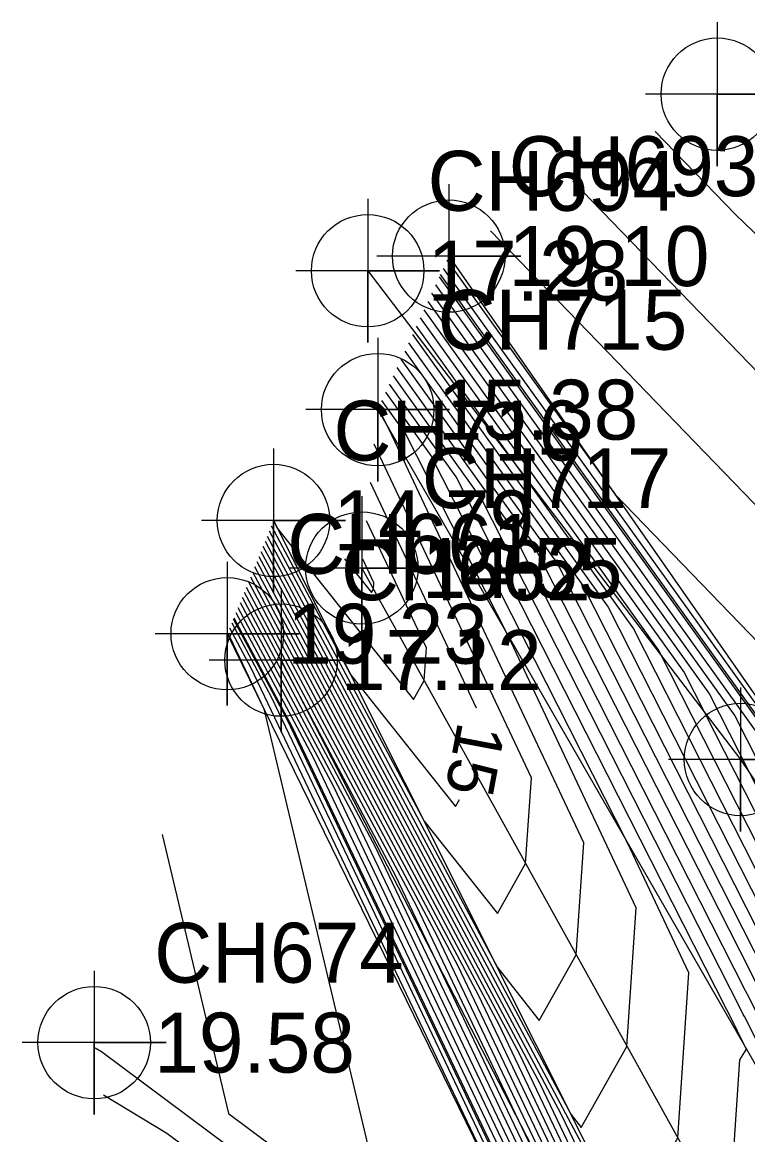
# Model space of a CAD drawing. Extents: x 2531902 to 2533249, y 715219 to 716099.
# Drawn here: x 2532631.93 to 2532662.18, y 715724.93 to 715771.34 of the extents above; entities that cross this region are included whole.
import ezdxf

# ---------------------------------------------------------------- set-up
doc = ezdxf.new("R2010")
doc.units = 0
for name, color, linetype in [('DTM Contours Major', 7, 'Continuous'), ('DTM Contours Major Text', 7, 'Continuous'), ('DTM Contours Minor', 7, 'Continuous'), ('Exist DTM Breakline', 7, 'Continuous'), ('Exist DTM Breakline Cogo Elevation', 7, 'Continuous'), ('Exist DTM Breakline Cogo Number', 7, 'Continuous'), ('Exist DTM Breakline Cogo Point CELL', 7, 'Continuous'), ('Exist DTM Breakline Underwater', 7, 'Continuous'), ('Exist DTM Breakline Underwater Cogo Elevation', 7, 'Continuous'), ('Exist DTM Breakline Underwater Cogo Number', 7, 'Continuous'), ('Exist DTM Breakline Underwater Cogo Point CELL', 7, 'Continuous'), ('Exist DTM Drainline', 7, 'Continuous'), ('Exist DTM Drainline Cogo Elevation', 7, 'Continuous'), ('Exist DTM Drainline Cogo Number', 7, 'Continuous'), ('Exist DTM Drainline Cogo Point CELL', 7, 'Continuous'), ('Exist DTM Regular Point CELL', 7, 'Continuous'), ('Exist DTM Regular Point Cogo Elevation', 7, 'Continuous'), ('Exist DTM Regular Point Cogo Number', 7, 'Continuous'), ('Exist Hydro Stream or Body of Water', 7, 'Continuous'), ('Scratch_Level_2', 7, 'Continuous')]:
    doc.layers.add(name, color=color, linetype=linetype)

msp = doc.modelspace()

# ---------------------------------------------------------------- linework, layer by layer
at = {"layer": 'DTM Contours Major'}
for points in [[(2532649.633, 715761.418), (2532652.853, 715756.928), (2532656.657, 715751.625), (2532664.623, 715743.377), (2532667.706, 715740.404), (2532666.809, 715739.156), (2532666.528, 715738.511), (2532668.94, 715733.933), (2532672.977, 715727.234), (2532680.368, 715714.969), (2532681.544, 715712.977), (2532683.635, 715709.501), (2532686.333, 715705.014), (2532690.675, 715692.977), (2532694.04, 715683.649), (2532695.571, 715678.45), (2532696.057, 715676.798), (2532696.595, 715675.745)], [(2532648.836, 715759.695), (2532660.585, 715743.315), (2532663.46, 715737.646), (2532664.163, 715736.258), (2532664.6, 715735.397), (2532666.384, 715731.88), (2532676.095, 715715.765), (2532678.43, 715711.81), (2532679.978, 715709.189), (2532683.024, 715704.123), (2532687.927, 715690.534), (2532690.367, 715682.244), (2532692.007, 715676.673), (2532692.528, 715674.904), (2532693.303, 715672.271), (2532693.837, 715671.226)], [(2532648.039, 715757.973), (2532655.303, 715747.844), (2532662.601, 715733.455), (2532662.956, 715732.756), (2532663.176, 715732.322), (2532667.705, 715723.393), (2532671.821, 715716.561), (2532677.749, 715706.522), (2532678.412, 715705.4), (2532679.715, 715703.233), (2532681.813, 715697.419), (2532688.008, 715676.376), (2532688.443, 715674.897), (2532688.581, 715674.428), (2532690.418, 715668.187)], [(2532660.847, 715720.061), (2532661.369, 715720.986), (2532661.843, 715728.055), (2532662.127, 715728.507), (2532661.752, 715729.246), (2532661.749, 715729.253), (2532661.743, 715729.264), (2532650.022, 715752.374), (2532647.242, 715756.25)], [(2532650.874, 715742.727), (2532646.444, 715752.142)], [(2532642.313, 715750.336), (2532642.435, 715750.107), (2532645.621, 715744.129), (2532649.988, 715738.623), (2532650.157, 715738.922)], [(2532641.879, 715749.271), (2532642.582, 715747.953), (2532654.386, 715725.807), (2532655.602, 715723.253), (2532655.639, 715723.186), (2532658.571, 715717.835), (2532658.688, 715717.589), (2532658.784, 715717.42), (2532659.861, 715715.532), (2532661.796, 715713.217), (2532661.216, 715716.117)], [(2532641.445, 715748.207), (2532642.728, 715745.799), (2532650.078, 715732.01), (2532654.945, 715721.787), (2532655.093, 715721.516), (2532656.919, 715718.185), (2532657.882, 715716.157), (2532658.675, 715714.767), (2532667.547, 715699.217), (2532670.158, 715696.092), (2532671.345, 715689.97), (2532675.473, 715673.874), (2532678.887, 715665.633), (2532678.986, 715665.315), (2532678.994, 715665.289), (2532680.646, 715661.305), (2532681.253, 715660.451), (2532682.935, 715658.087)], [(2532641.011, 715747.142), (2532642.875, 715743.645), (2532645.77, 715738.213), (2532654.289, 715720.32), (2532654.548, 715719.847), (2532655.267, 715718.535), (2532657.076, 715714.724), (2532658.566, 715712.113), (2532663.486, 715703.49), (2532667.906, 715693.389), (2532668.844, 715689.728), (2532671.192, 715680.572), (2532678.057, 715664.003), (2532678.096, 715663.878), (2532678.112, 715663.825), (2532681.367, 715655.975)], [(2532640.577, 715746.077), (2532641.462, 715744.416), (2532652.721, 715720.768), (2532653.102, 715719.165), (2532653.606, 715718.788), (2532656.082, 715713.258), (2532657.678, 715709.829), (2532661.76, 715700.501), (2532666.009, 715690.79), (2532666.911, 715687.27), (2532675.713, 715666.027), (2532677.227, 715662.373), (2532677.231, 715662.362), (2532677.954, 715660.618), (2532679.854, 715656.035), (2532678.345, 715656.509)]]:
    msp.add_lwpolyline(points, dxfattribs=at)
at = {"layer": 'DTM Contours Minor'}
for points in [[(2532658.323, 715766.785), (2532661.653, 715763.337), (2532679.963, 715745.68), (2532674.634, 715738.272), (2532672.968, 715734.443), (2532681.775, 715717.727), (2532684.122, 715715.936)], [(2532654.889, 715764.712), (2532662.643, 715756.684), (2532675.877, 715743.921), (2532672.025, 715738.567), (2532670.822, 715735.799), (2532681.174, 715716.15), (2532681.493, 715715.62), (2532682.077, 715714.65), (2532682.17, 715714.493), (2532686.651, 715707.042)], [(2532651.454, 715762.64), (2532663.633, 715750.031), (2532671.792, 715742.162), (2532669.417, 715738.861), (2532668.675, 715737.155), (2532675.057, 715725.042), (2532677.235, 715721.427), (2532681.222, 715714.809), (2532681.857, 715713.735), (2532685.143, 715708.271)], [(2532649.473, 715761.074), (2532659.233, 715747.467), (2532664.81, 715739.691), (2532665.129, 715739.06), (2532665.328, 715738.669), (2532668.719, 715733.041), (2532679.513, 715715.128), (2532681.23, 715712.22), (2532682.127, 715710.73), (2532685.671, 715704.836)], [(2532649.314, 715760.729), (2532663.753, 715740.597), (2532663.975, 715740.161), (2532664.888, 715738.36), (2532665.455, 715737.242), (2532665.592, 715736.972), (2532678.659, 715715.287), (2532678.838, 715714.983), (2532680.917, 715711.462), (2532685.01, 715704.658)], [(2532648.995, 715760.04), (2532661.641, 715742.409), (2532663.631, 715738.484), (2532664.405, 715736.959), (2532664.885, 715736.012), (2532666.12, 715733.577), (2532676.949, 715715.606), (2532678.566, 715712.868), (2532680.291, 715709.947), (2532683.686, 715704.302)], [(2532649.155, 715760.385), (2532662.697, 715741.503), (2532663.803, 715739.323), (2532664.646, 715737.659), (2532665.17, 715736.627), (2532665.856, 715735.275), (2532677.804, 715715.447), (2532678.702, 715713.925), (2532680.604, 715710.704), (2532684.348, 715704.48)], [(2532648.676, 715759.351), (2532659.528, 715744.221), (2532663.288, 715736.808), (2532663.922, 715735.558), (2532664.315, 715734.782), (2532666.648, 715730.183), (2532675.24, 715715.924), (2532678.294, 715710.752), (2532679.664, 715708.431), (2532682.362, 715703.945), (2532686.704, 715691.911)], [(2532648.358, 715758.662), (2532657.416, 715746.032), (2532662.945, 715735.132), (2532663.439, 715734.157), (2532663.746, 715733.552), (2532667.176, 715726.788), (2532673.531, 715716.243), (2532678.022, 715708.637), (2532679.038, 715706.916), (2532681.039, 715703.589), (2532684.258, 715694.665)], [(2532648.517, 715759.006), (2532658.472, 715745.126), (2532663.116, 715735.97), (2532663.68, 715734.857), (2532664.031, 715734.167), (2532666.912, 715728.485), (2532674.385, 715716.084), (2532678.158, 715709.695), (2532679.351, 715707.673), (2532681.701, 715703.767), (2532685.481, 715693.288)], [(2532648.198, 715758.317), (2532656.36, 715746.938), (2532662.773, 715734.293), (2532663.198, 715733.456), (2532663.461, 715732.937), (2532667.44, 715725.091), (2532672.676, 715716.402), (2532677.886, 715707.579), (2532678.725, 715706.158), (2532680.377, 715703.411), (2532683.035, 715696.042)], [(2532647.88, 715757.628), (2532654.247, 715748.75), (2532662.43, 715732.617), (2532662.715, 715732.055), (2532662.891, 715731.707), (2532667.969, 715721.696), (2532670.967, 715716.721), (2532677.613, 715705.464), (2532678.098, 715704.643), (2532679.053, 715703.055), (2532680.59, 715698.796), (2532687.536, 715675.203)], [(2532647.72, 715757.283), (2532653.191, 715749.656), (2532662.258, 715731.779), (2532662.473, 715731.355), (2532662.606, 715731.092), (2532668.233, 715719.999), (2532670.112, 715716.88), (2532677.477, 715704.406), (2532677.785, 715703.885), (2532678.391, 715702.877), (2532679.367, 715700.173), (2532686.165, 715677.082)], [(2532668.497, 715718.301), (2532662.322, 715730.477), (2532662.232, 715730.654), (2532662.086, 715730.941), (2532652.135, 715750.562), (2532647.561, 715756.939)], [(2532641.792, 715749.059), (2532642.611, 715747.522), (2532653.524, 715727.048), (2532655.47, 715722.96), (2532655.53, 715722.852), (2532658.24, 715717.905), (2532658.527, 715717.303), (2532658.762, 715716.89), (2532661.398, 715712.269), (2532666.133, 715706.603), (2532664.574, 715714.399), (2532665.75, 715717.772), (2532667.089, 715719.901), (2532662.037, 715729.861), (2532661.99, 715729.954), (2532661.915, 715730.102), (2532651.078, 715751.468), (2532647.402, 715756.594)], [(2532641.966, 715749.484), (2532642.552, 715748.384), (2532655.247, 715724.567), (2532655.733, 715723.547), (2532655.748, 715723.52), (2532657.854, 715719.676), (2532657.802, 715722.225), (2532658.26, 715723.037), (2532659.256, 715724.802), (2532659.717, 715731.69), (2532657.165, 715737.113), (2532648.966, 715753.28), (2532647.083, 715755.905)], [(2532642.052, 715749.697), (2532642.523, 715748.815), (2532654.796, 715725.789), (2532655.234, 715725.236), (2532657.142, 715728.618), (2532657.529, 715734.4), (2532652.204, 715745.719), (2532647.91, 715754.186), (2532646.923, 715755.561)], [(2532642.139, 715749.91), (2532642.494, 715749.245), (2532651.738, 715731.903), (2532653.486, 715729.699), (2532655.028, 715732.433), (2532655.342, 715737.11), (2532647.242, 715754.325), (2532646.853, 715755.092), (2532646.764, 715755.216)], [(2532642.226, 715750.123), (2532642.464, 715749.676), (2532648.68, 715738.016), (2532651.737, 715734.161), (2532652.915, 715736.249), (2532653.154, 715739.82), (2532646.604, 715753.741)], [(2532642.4, 715750.549), (2532642.406, 715750.538), (2532642.563, 715750.242), (2532648.239, 715743.086), (2532648.688, 715743.881), (2532648.779, 715745.241), (2532646.285, 715750.542)], [(2532641.705, 715748.846), (2532642.64, 715747.091), (2532652.663, 715728.288), (2532655.339, 715722.667)], [(2532645.369, 715748.962), (2532646.49, 715747.548), (2532646.574, 715747.697), (2532646.591, 715747.951), (2532646.125, 715748.942)], [(2532641.532, 715748.42), (2532642.699, 715746.23), (2532650.939, 715730.77), (2532655.076, 715722.08), (2532655.202, 715721.85), (2532657.249, 715718.115), (2532658.043, 715716.443), (2532658.697, 715715.297), (2532666.01, 715702.48), (2532670.839, 715696.701), (2532673.036, 715685.378), (2532676.329, 715672.534), (2532679.053, 715665.959), (2532679.164, 715665.603), (2532679.17, 715665.581), (2532680.495, 715662.386), (2532680.982, 715661.701), (2532692.247, 715645.871)], [(2532641.618, 715748.633), (2532642.669, 715746.661), (2532651.801, 715729.529), (2532655.208, 715722.373), (2532655.311, 715722.184), (2532657.58, 715718.045), (2532658.204, 715716.73), (2532658.719, 715715.828), (2532664.473, 715705.743), (2532671.52, 715697.309), (2532674.726, 715680.785), (2532677.185, 715671.195), (2532679.219, 715666.285), (2532679.342, 715665.89), (2532679.347, 715665.874), (2532680.344, 715663.467), (2532680.711, 715662.952), (2532693.194, 715645.41)], [(2532641.358, 715747.994), (2532642.757, 715745.368), (2532649.216, 715733.251), (2532654.814, 715721.493), (2532654.984, 715721.183), (2532656.588, 715718.255), (2532657.721, 715715.87), (2532658.653, 715714.236), (2532669.084, 715695.954), (2532669.477, 715695.484), (2532669.655, 715694.563), (2532674.616, 715675.213), (2532678.721, 715665.307), (2532678.808, 715665.028), (2532678.818, 715664.996), (2532680.796, 715660.223), (2532681.524, 715659.201), (2532690.353, 715646.793)], [(2532641.184, 715747.568), (2532642.816, 715744.507), (2532647.493, 715735.732), (2532654.551, 715720.907), (2532654.766, 715720.515), (2532655.928, 715718.395), (2532657.399, 715715.297), (2532658.61, 715713.174), (2532666.557, 715699.245), (2532668.664, 715694.429), (2532669.112, 715692.683), (2532672.904, 715677.893), (2532678.389, 715664.655), (2532678.452, 715664.453), (2532678.465, 715664.411), (2532681.097, 715658.06), (2532682.066, 715656.7), (2532688.459, 715647.716)], [(2532641.271, 715747.781), (2532642.787, 715744.937), (2532648.355, 715734.491), (2532654.682, 715721.2), (2532654.875, 715720.849), (2532656.258, 715718.325), (2532657.56, 715715.584), (2532658.632, 715713.705), (2532668.092, 715697.123), (2532669.044, 715694.948), (2532669.246, 715694.16), (2532673.76, 715676.553), (2532678.555, 715664.981), (2532678.63, 715664.74), (2532678.641, 715664.703), (2532680.947, 715659.142), (2532681.795, 715657.95), (2532689.406, 715647.255)], [(2532641.097, 715747.355), (2532642.845, 715744.076), (2532646.632, 715736.972), (2532654.42, 715720.613), (2532654.657, 715720.181), (2532655.597, 715718.465), (2532657.238, 715715.011), (2532658.588, 715712.644), (2532665.021, 715701.368), (2532668.285, 715693.909), (2532668.978, 715691.205), (2532672.048, 715679.232), (2532678.223, 715664.329), (2532678.274, 715664.165), (2532678.289, 715664.118), (2532681.248, 715656.979), (2532682.336, 715655.45), (2532687.512, 715648.177)], [(2532640.75, 715746.503), (2532642.963, 715742.353), (2532643.185, 715741.935), (2532653.895, 715719.44), (2532654.22, 715718.846), (2532654.276, 715718.745), (2532656.593, 715713.865), (2532658.501, 715710.521), (2532658.879, 715709.857), (2532666.768, 715691.829), (2532668.443, 715685.295), (2532668.624, 715684.591), (2532677.559, 715663.025), (2532677.562, 715663.015), (2532677.584, 715662.947), (2532681.851, 715652.654), (2532683.42, 715650.449)], [(2532640.837, 715746.716), (2532642.933, 715742.783), (2532644.047, 715740.694), (2532654.026, 715719.733), (2532654.329, 715719.179), (2532654.606, 715718.675), (2532656.754, 715714.151), (2532658.523, 715711.051), (2532660.415, 715707.735), (2532667.147, 715692.349), (2532668.577, 715686.772), (2532669.48, 715683.251), (2532677.725, 715663.351), (2532677.74, 715663.303), (2532677.76, 715663.24), (2532681.7, 715653.735), (2532683.149, 715651.699)], [(2532640.924, 715746.929), (2532642.904, 715743.214), (2532644.908, 715739.454), (2532654.157, 715720.026), (2532654.439, 715719.513), (2532654.936, 715718.605), (2532656.915, 715714.438), (2532658.544, 715711.582), (2532661.95, 715705.613), (2532667.526, 715692.869), (2532668.711, 715688.25), (2532670.336, 715681.911), (2532677.891, 715663.677), (2532677.918, 715663.59), (2532677.936, 715663.532), (2532681.549, 715654.816), (2532682.878, 715652.949)], [(2532640.663, 715746.29), (2532642.324, 715743.175), (2532647.781, 715731.712), (2532653.763, 715719.146), (2532653.945, 715718.815), (2532655.324, 715715.911), (2532656.432, 715713.578), (2532657.344, 715711.98), (2532659.894, 715706.151), (2532666.388, 715691.31), (2532667.767, 715685.93), (2532671.54, 715676.826), (2532677.393, 715662.699), (2532677.407, 715662.654), (2532680.202, 715655.912), (2532682.001, 715651.572), (2532682.777, 715650.482)], [(2532640.49, 715745.864), (2532640.601, 715745.656), (2532642.009, 715742.698), (2532646.814, 715722.49), (2532653.178, 715717.743), (2532655.358, 715712.87), (2532661.7, 715699.251), (2532663.625, 715694.851), (2532665.629, 715690.27), (2532666.055, 715688.609), (2532672.161, 715673.875), (2532658.219, 715685.571), (2532656.426, 715685.285), (2532656.404, 715684.989), (2532656.419, 715684.664), (2532656.422, 715684.554), (2532656.488, 715684.349), (2532675.709, 715662.676)], [(2532637.757, 715737.465), (2532640.527, 715725.815), (2532652.749, 715716.698), (2532654.635, 715712.483), (2532665.04, 715690.137), (2532655.559, 715688.62), (2532655.426, 715686.873), (2532655.514, 715684.958), (2532655.534, 715684.308), (2532655.922, 715683.097), (2532673.465, 715663.315), (2532673.508, 715661.778), (2532667.044, 715656.745), (2532667.353, 715654.235), (2532669.684, 715653.453), (2532672.388, 715651.419), (2532681.538, 715647.888), (2532691.256, 715639.168)], [(2532634.969, 715728.558), (2532635.232, 715728.4), (2532652.32, 715715.653), (2532653.912, 715712.096), (2532662.693, 715693.236), (2532654.692, 715691.956), (2532654.448, 715688.758), (2532654.61, 715685.252), (2532654.646, 715684.061), (2532655.355, 715681.845), (2532671.222, 715663.954), (2532671.29, 715661.486), (2532665.888, 715657.28), (2532666.335, 715653.648), (2532669.706, 715652.517), (2532673.617, 715649.576), (2532681.29, 715646.615), (2532689.439, 715639.303)], [(2532635.316, 715726.593), (2532637.962, 715724.999), (2532651.891, 715714.608), (2532653.189, 715711.708), (2532660.347, 715696.335), (2532653.824, 715695.292), (2532653.469, 715690.642), (2532653.705, 715685.546), (2532653.757, 715683.815), (2532654.789, 715680.592), (2532668.978, 715664.593), (2532669.073, 715661.194), (2532664.731, 715657.814), (2532665.316, 715653.061), (2532669.728, 715651.581), (2532674.845, 715647.732), (2532681.042, 715645.341), (2532687.622, 715639.437)]]:
    msp.add_lwpolyline(points, dxfattribs=at)
at = {"layer": 'Exist DTM Breakline'}
for points in [[(2532649.711, 715761.588), (2532665.224, 715739.335), (2532688.443, 715705.582), (2532697.711, 715679.516), (2532703.673, 715665.533), (2532716.286, 715652.801)], [(2532640.477, 715745.834), (2532656.325, 715713.388), (2532665.291, 715689.806), (2532682.108, 715650.808), (2532695.585, 715638.849), (2532713.668, 715632.91)]]:
    msp.add_lwpolyline(points, dxfattribs=at)
at = {"layer": 'Exist DTM Breakline Cogo Point CELL'}
for points in [[(2532649.711, 715764.588), (2532649.711, 715758.588), (2532649.711, 715761.588), (2532652.711, 715761.588), (2532646.711, 715761.588)], [(2532646.331, 715763.978), (2532646.331, 715757.978), (2532646.331, 715760.978), (2532649.331, 715760.978), (2532643.331, 715760.978)], [(2532640.477, 715748.834), (2532640.477, 715742.834), (2532640.477, 715745.834), (2532643.477, 715745.834), (2532637.477, 715745.834)], [(2532642.721, 715747.733), (2532642.721, 715741.733), (2532642.721, 715744.733), (2532645.721, 715744.733), (2532639.721, 715744.733)], [(2532661.875, 715743.587), (2532661.875, 715737.587), (2532661.875, 715740.587), (2532664.875, 715740.587), (2532658.875, 715740.587)]]:
    msp.add_lwpolyline(points, dxfattribs=at)
for centre in [(2532649.711, 715761.588), (2532646.331, 715760.978), (2532640.477, 715745.834), (2532642.721, 715744.733), (2532661.875, 715740.587)]:
    msp.add_circle(centre, 2.344, dxfattribs=at)
at = {"layer": 'Exist DTM Breakline Underwater'}
for points in [[(2532646.748, 715755.182), (2532668.676, 715717.147), (2532677.241, 715702.567), (2532689.842, 715666.582), (2532701.723, 715652.924), (2532713.134, 715647.155), (2532737.59, 715643.253), (2532756.176, 715636.457), (2532783.406, 715639.452), (2532803.254, 715642.171), (2532813.801, 715644.931), (2532836.277, 715651.081), (2532865.559, 715653.815), (2532885.826, 715645.124), (2532889.946, 715643.683), (2532906.865, 715630.423), (2532927.34, 715618.228), (2532957.965, 715607.729), (2532978.566, 715598.571), (2533001.091, 715586.568), (2533028.19, 715572.821)], [(2532642.404, 715750.56), (2532658.799, 715717.787), (2532669.356, 715695.376), (2532679.885, 715666.767), (2532697.228, 715643.446), (2532713.346, 715638.817), (2532732.829, 715632.464), (2532756.843, 715626.148), (2532779.072, 715626.28), (2532796.688, 715625.652), (2532823.757, 715631.859), (2532837.11, 715635.289), (2532855.521, 715634.196), (2532877.341, 715623.453), (2532903.322, 715612.979), (2532923.748, 715606.844), (2532938.002, 715599.697), (2532947.164, 715595.611), (2532973.382, 715584.595), (2532998.348, 715572.794), (2533019.077, 715559.415)]]:
    msp.add_lwpolyline(points, dxfattribs=at)
at = {"layer": 'Exist DTM Breakline Underwater Cogo Point CELL'}
for points in [[(2532646.748, 715758.182), (2532646.748, 715752.182), (2532646.748, 715755.182), (2532649.748, 715755.182), (2532643.748, 715755.182)], [(2532642.404, 715753.56), (2532642.404, 715747.56), (2532642.404, 715750.56), (2532645.404, 715750.56), (2532639.404, 715750.56)]]:
    msp.add_lwpolyline(points, dxfattribs=at)
for centre in [(2532646.748, 715755.182), (2532642.404, 715750.56)]:
    msp.add_circle(centre, 2.344, dxfattribs=at)
at = {"layer": 'Exist DTM Drainline'}
msp.add_lwpolyline([(2532646.088, 715748.574), (2532662.801, 715718.401), (2532671.966, 715697.708), (2532683.278, 715666.632), (2532699.337, 715647.34), (2532712.159, 715642.172)], dxfattribs=at)
at = {"layer": 'Exist DTM Drainline Cogo Point CELL'}
msp.add_lwpolyline([(2532646.088, 715751.574), (2532646.088, 715745.574), (2532646.088, 715748.574), (2532649.088, 715748.574), (2532643.088, 715748.574)], dxfattribs=at)
msp.add_circle((2532646.088, 715748.574), 2.344, dxfattribs=at)
at = {"layer": 'Exist DTM Regular Point CELL'}
for points in [[(2532660.908, 715771.344), (2532660.908, 715765.344), (2532660.908, 715768.344), (2532663.908, 715768.344), (2532657.908, 715768.344)], [(2532634.931, 715731.775), (2532634.931, 715725.775), (2532634.931, 715728.775), (2532637.931, 715728.775), (2532631.931, 715728.775)]]:
    msp.add_lwpolyline(points, dxfattribs=at)
for centre in [(2532660.908, 715768.344), (2532634.931, 715728.775)]:
    msp.add_circle(centre, 2.344, dxfattribs=at)
at = {"layer": 'Exist Hydro Stream or Body of Water'}
for points in [[(2532649.354, 715760.815), (2532664.017, 715740.37), (2532664.948, 715738.535), (2532665.526, 715737.396), (2532678.872, 715715.247), (2532680.996, 715711.651), (2532685.175, 715704.702), (2532691.901, 715686.059), (2532694.324, 715677.828), (2532695.093, 715675.214), (2532699.89, 715665.82), (2532703.016, 715661.283), (2532714.635, 715652.814), (2532715.929, 715652.16), (2532727.227, 715650.963), (2532730.055, 715650.803), (2532751.801, 715642.405), (2532753.898, 715641.752), (2532766.592, 715639.773), (2532767.187, 715639.811), (2532779.493, 715644.52), (2532786.898, 715645.569), (2532790.115, 715646.495), (2532806.64, 715649.775)], [(2532640.729, 715746.45), (2532642.97, 715742.245), (2532653.862, 715719.366), (2532654.193, 715718.762), (2532656.553, 715713.793), (2532658.495, 715710.388), (2532666.673, 715691.699), (2532668.41, 715684.926), (2532677.518, 715662.944), (2532677.539, 715662.874), (2532681.888, 715652.383), (2532683.487, 715650.136)]]:
    msp.add_lwpolyline(points, dxfattribs=at)
at = {"layer": 'Scratch_Level_2'}
for points in [[(2532646.331, 715760.978), (2532661.875, 715740.587), (2532684.759, 715706.615), (2532696, 715677.679), (2532701.748, 715665.356), (2532714.118, 715649.677)], [(2532642.721, 715744.733), (2532658.993, 715713.136), (2532668.965, 715688.516), (2532685.182, 715651.328), (2532698.305, 715639.86), (2532714.664, 715634.736)]]:
    msp.add_lwpolyline(points, dxfattribs=at)

# ---------------------------------------------------------------- texts
at = {"layer": 'DTM Contours Major Text'}
msp.add_text('15', height=2, rotation=259.3239, dxfattribs=at).set_placement((2532650.105, 715742.214))
at = {"layer": 'Exist DTM Breakline Cogo Elevation'}
for s, p in [('19.10', (2532652.211, 715760.338)), ('17.28', (2532648.831, 715759.728)), ('19.23', (2532642.977, 715744.584)), ('17.12', (2532645.221, 715743.483))]:
    msp.add_text(s, height=2.5, dxfattribs=at).set_placement(p)
at = {"layer": 'Exist DTM Breakline Cogo Number'}
for s, p in [('CH693', (2532652.211, 715764.088)), ('CH694', (2532648.831, 715763.478)), ('CH661', (2532642.977, 715748.334)), ('CH662', (2532645.221, 715747.233))]:
    msp.add_text(s, height=2.5, dxfattribs=at).set_placement(p)
at = {"layer": 'Exist DTM Breakline Underwater Cogo Elevation'}
for s, p in [('15.38', (2532649.248, 715753.932)), ('14.79', (2532644.904, 715749.31))]:
    msp.add_text(s, height=2.5, dxfattribs=at).set_placement(p)
at = {"layer": 'Exist DTM Breakline Underwater Cogo Number'}
for s, p in [('CH715', (2532649.248, 715757.682)), ('CH716', (2532644.904, 715753.06))]:
    msp.add_text(s, height=2.5, dxfattribs=at).set_placement(p)
at = {"layer": 'Exist DTM Drainline Cogo Elevation'}
msp.add_text('14.55', height=2.5, dxfattribs=at).set_placement((2532648.588, 715747.324))
at = {"layer": 'Exist DTM Drainline Cogo Number'}
msp.add_text('CH717', height=2.5, dxfattribs=at).set_placement((2532648.588, 715751.074))
at = {"layer": 'Exist DTM Regular Point Cogo Elevation'}
msp.add_text('19.58', height=2.5, dxfattribs=at).set_placement((2532637.431, 715727.525))
at = {"layer": 'Exist DTM Regular Point Cogo Number'}
msp.add_text('CH674', height=2.5, dxfattribs=at).set_placement((2532637.431, 715731.275))

doc.saveas('drawing.dxf')
